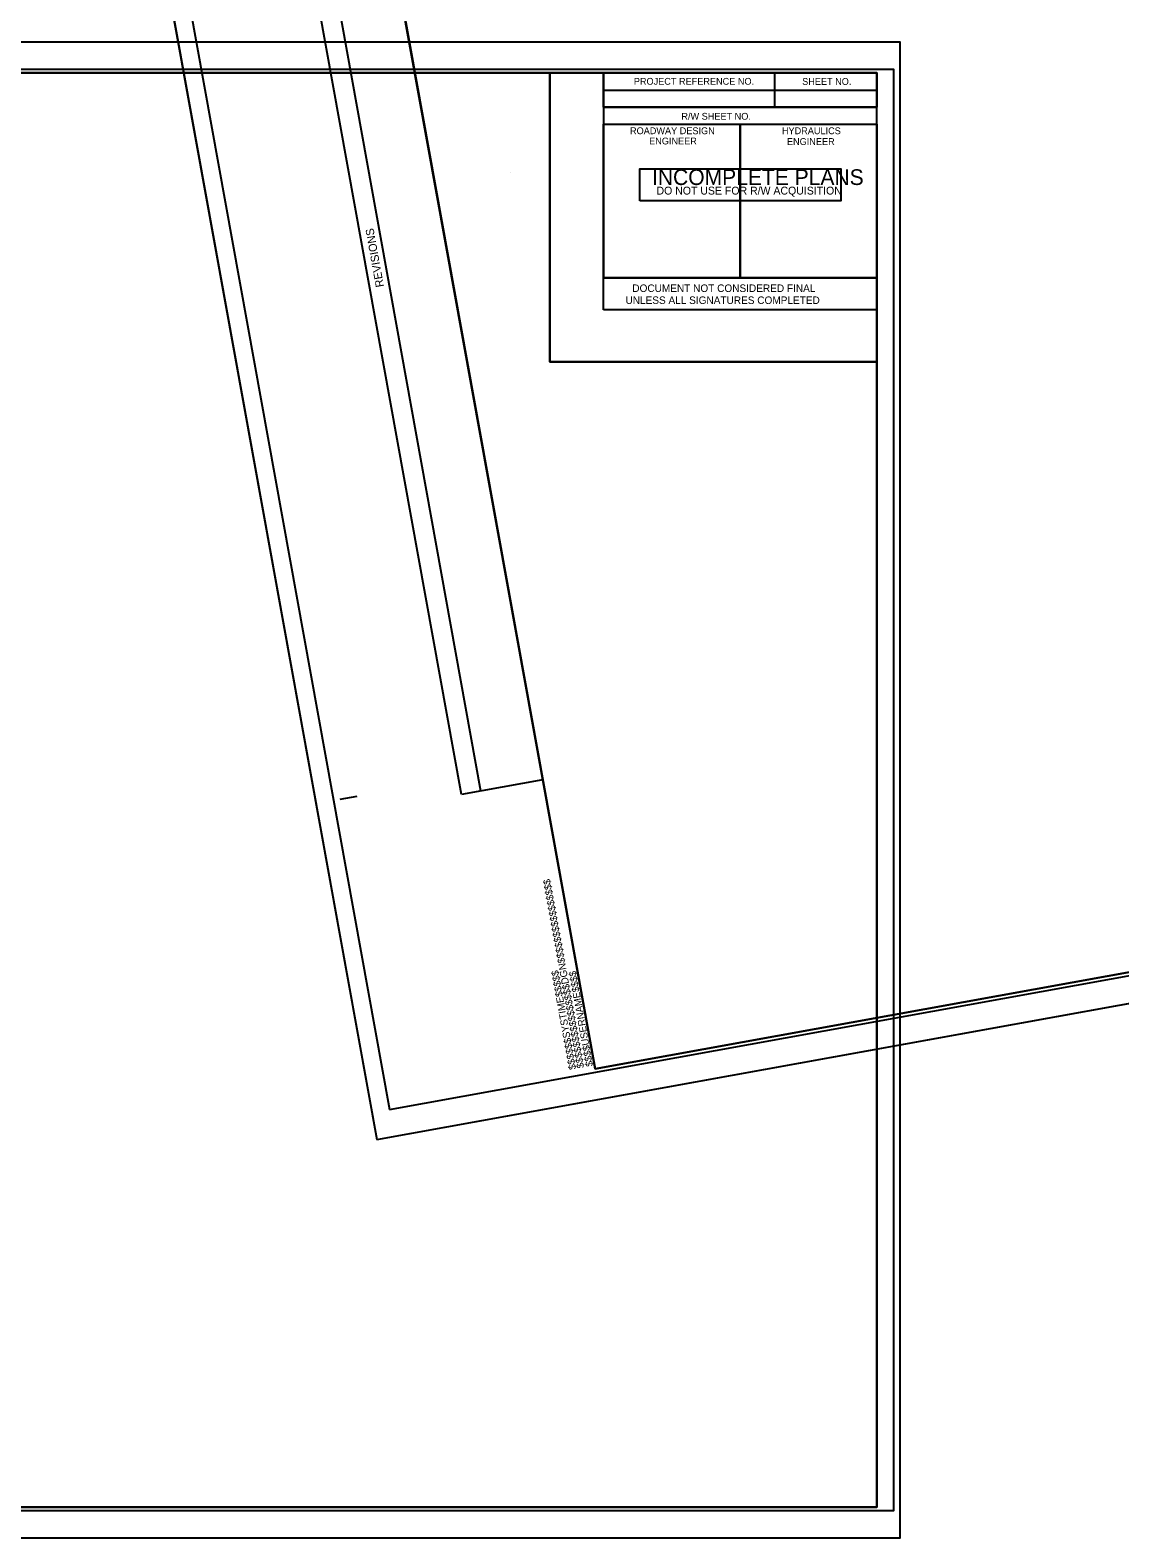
# Model space of a CAD drawing. Extents: x 1617779 to 1622406, y 896496 to 899510.
# Drawn here: x 1620092 to 1620890, y 897376 to 898480 of the extents above; entities that cross this region are included whole.
import ezdxf

# ---------------------------------------------------------------- set-up
doc = ezdxf.new("R2010")
doc.units = 0
for name, color, linetype in [('ControlPoints', 7, 'Continuous'), ('Exist Profile Cell', 7, 'Continuous'), ('Exist Vertical Profile Ground Line', 7, 'Continuous'), ('Exist Vertical Profile Horizontal Axis Label Major', 7, 'Continuous'), ('Observations', 7, 'Continuous'), ('Prop Horizontal Alignment', 7, 'Continuous'), ('Prop Horizontal Alignment Curve and Spiral Data', 7, 'Continuous'), ('Scratch_Level_4', 7, 'Continuous'), ('Setups', 7, 'Continuous')]:
    doc.layers.add(name, color=color, linetype=linetype)

msp = doc.modelspace()

# ---------------------------------------------------------------- linework, layer by layer
at = {"layer": 'ControlPoints'}
for points in [[(1620345.8, 897667.3), (1622002.3, 897967.2), (1621807.3, 899044.7), (1620150.7, 898744.8)], [(1619045.3, 897375.8), (1620728.8, 897375.8), (1620728.8, 898470.8), (1619045.3, 898470.8)]]:
    msp.add_lwpolyline(points, close=True, dxfattribs=at)
at = {"layer": 'Exist Profile Cell'}
for p, q in [((1620511.8, 898274.7), (1620511.8, 898298.2)), ((1620511.8, 898298.2), (1620711.8, 898298.2)), ((1620511.8, 898274.7), (1620511.8, 898298.2)), ((1620511.8, 898298.2), (1620711.8, 898298.2)), ((1620711.8, 898298.2), (1620711.8, 898274.7)), ((1620711.8, 898298.2), (1620711.8, 898274.7)), ((1620711.8, 898274.7), (1620511.8, 898274.7)), ((1620711.8, 898274.7), (1620511.8, 898274.7))]:
    msp.add_line(p, q, dxfattribs=at)
at = {"layer": 'Exist Vertical Profile Ground Line'}
msp.add_line((1620422, 897922.5), (1620281.2, 898700.5), dxfattribs=at)
msp.add_lwpolyline([(1620407.7, 897919.9), (1620266.9, 898697.9), (1620326.5, 898708.7), (1620467.3, 897930.7)], close=True, dxfattribs=at)
at = {"layer": 'Exist Vertical Profile Horizontal Axis Label Major'}
for p, q in [((1620636.8, 898448.2), (1620636.8, 898423.2)), ((1620511.7, 898435.7), (1620711.8, 898435.7)), ((1620511.7, 898423.2), (1620711.8, 898423.2)), ((1620511.7, 898423.2), (1620511.7, 898410.7)), ((1620511.7, 898423.2), (1620711.8, 898423.2)), ((1620611.8, 898410.7), (1620611.8, 898298.3)), ((1620319, 897916.5), (1620331.3, 897918.7)), ((1620505.6, 897719.1), (1620505.6, 897719.1))]:
    msp.add_line(p, q, dxfattribs=at)
for points in [[(1621794.6, 899019.5), (1620318.6, 898752.3), (1620505.6, 897719.1), (1621981.6, 897986.3)], [(1620505.6, 897719.1), (1620318.5, 898752.3), (1621597.7, 898983.9), (1621624.5, 898836.2), (1621821.3, 898871.9), (1621981.6, 897986.3)], [(1620711.8, 898448.3), (1619211.8, 898448.3), (1619211.8, 897398.3), (1620711.8, 897398.3)], [(1619211.8, 897398.3), (1619211.8, 898448.3), (1620511.7, 898448.3), (1620511.8, 898298.2), (1620711.8, 898298.2), (1620711.8, 897398.3)], [(1620511.7, 898448.3), (1620711.8, 898448.3), (1620711.8, 898423.2), (1620511.7, 898423.2)], [(1620511.7, 898410.7), (1620611.8, 898410.7), (1620611.8, 898298.2), (1620511.8, 898298.2)], [(1620611.8, 898410.7), (1620711.8, 898410.7), (1620711.8, 898298.2), (1620611.8, 898298.2)]]:
    msp.add_lwpolyline(points, close=True, dxfattribs=at)
at = {"layer": 'Observations'}
for points in [[(1620318.5, 898752.3), (1620505.6, 897719.1), (1621981.6, 897986.3), (1621832.2, 898811.4), (1621596.8, 898768.8), (1621559.1, 898976.9)], [(1619211.8, 898448.3), (1619211.8, 897398.3), (1620711.8, 897398.3), (1620711.8, 898236.8), (1620472.5, 898236.8), (1620472.5, 898448.3)], [(1620472.5, 898236.8), (1620711.8, 898236.8), (1620711.8, 898448.3), (1620472.5, 898448.3)]]:
    msp.add_lwpolyline(points, close=True, dxfattribs=at)
at = {"layer": 'Prop Horizontal Alignment'}
for p, q in [((1620150.7, 898744.8), (1620345.8, 897667.3)), ((1620728.8, 898470.8), (1619045.3, 898470.8)), ((1620345.8, 897667.3), (1622002.3, 897967.2)), ((1619045.3, 897375.8), (1620728.8, 897375.8))]:
    msp.add_line(p, q, dxfattribs=at)
at = {"layer": 'Prop Horizontal Alignment Curve and Spiral Data'}
msp.add_lwpolyline([(1620538.3, 898354.5), (1620538.3, 898378), (1620685.3, 898378), (1620685.3, 898354.5)], close=True, dxfattribs=at)
at = {"layer": 'Scratch_Level_4'}
msp.add_line((1620443.7, 898375.3), (1620443.7, 898375.3), dxfattribs=at)
at = {"layer": 'Setups'}
for points in [[(1620355, 897689.3), (1621994.3, 897986.1), (1621806.4, 899024.2), (1620167.1, 898727.5)], [(1619058.3, 897395.8), (1620724.3, 897395.8), (1620724.3, 898450.8), (1619058.3, 898450.8)]]:
    msp.add_lwpolyline(points, close=True, dxfattribs=at)

# ---------------------------------------------------------------- texts
at = {"layer": 'Exist Profile Cell'}
for s, p in [('DOCUMENT NOT CONSIDERED FINAL', (1620532.8, 898287.9)), ('DOCUMENT NOT CONSIDERED FINAL', (1620532.8, 898287.9)), ('UNLESS ALL SIGNATURES COMPLETED', (1620527.8, 898279.1)), ('UNLESS ALL SIGNATURES COMPLETED', (1620527.8, 898279.1))]:
    msp.add_text(s, height=5.5, dxfattribs=at).set_placement(p)
at = {"layer": 'Exist Vertical Profile Ground Line'}
msp.add_text('REVISIONS', height=6, rotation=100.2599, dxfattribs=at).set_placement((1620351.1, 898291.9))
at = {"layer": 'Exist Vertical Profile Horizontal Axis Label Major'}
for s, height, rotation, p in [('PROJECT REFERENCE NO.', 5, 0, (1620533.9, 898439.6)), ('SHEET NO.', 5, 0, (1620657.1, 898439.5)), ('R/W SHEET NO.', 5, 0, (1620568.7, 898414)), ('ROADWAY DESIGN', 5, 0, (1620531.1, 898403.4)), ('HYDRAULICS', 5, 0, (1620642.3, 898403.4)), ('ENGINEER', 5, 0, (1620545.1, 898395.9)), ('ENGINEER', 5, 0, (1620646, 898395.5)), ('$$$$$$$$$$$$$$$$DGN$$$$$$$$$$$$$$$$', 5.25, 100.26, (1620497.6, 897720.1)), ('$$$$$$SYSTIME$$$$$', 5.25, 100.26, (1620491.7, 897719)), ('$$$$USERNAME$$$$', 5.25, 100.26, (1620504.1, 897721.3))]:
    msp.add_text(s, height=height, rotation=rotation, dxfattribs=at).set_placement(p)
at = {"layer": 'Prop Horizontal Alignment Curve and Spiral Data'}
for s, height, p in [('INCOMPLETE PLANS', 11.52, (1620547.2, 898366.2)), ('DO NOT USE FOR R/W ACQUISITION', 5.76, (1620550.5, 898359.2))]:
    msp.add_text(s, height=height, dxfattribs=at).set_placement(p)

doc.saveas('drawing.dxf')
